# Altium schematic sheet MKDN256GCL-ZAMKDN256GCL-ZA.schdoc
size 127 x 101 mm
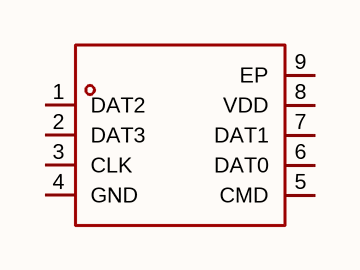
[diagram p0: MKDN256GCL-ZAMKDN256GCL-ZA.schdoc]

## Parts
U?  mkdn256gcl-za  [LGA-16_L12.5-W9.0-P1.27-TL-EP]  (value not drawn)

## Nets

Not connected (* = marked no-connect by the designer): U? 1(DAT2) 2(DAT3) 3(CLK) 4(GND) 5(CMD) 6(DAT0) 7(DAT1) 8(VDD) 9(EP)

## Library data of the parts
U? = mkdn256gcl-za: 存储容量:256Gbit;时钟频率(fc):208MHz;工作电压:2.7V~3.6V;; Manufacturer: MK(米客方德); AddInBom: yes; ModelId: aae4acadbbb4480ebd429fe2f08c27d7; ModelTransform: 492.125,354.33,0,0,0,0,0,0,0; Interface: SPI; Clock Frequency: 208MHz; Standby Supply Current: 250uA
